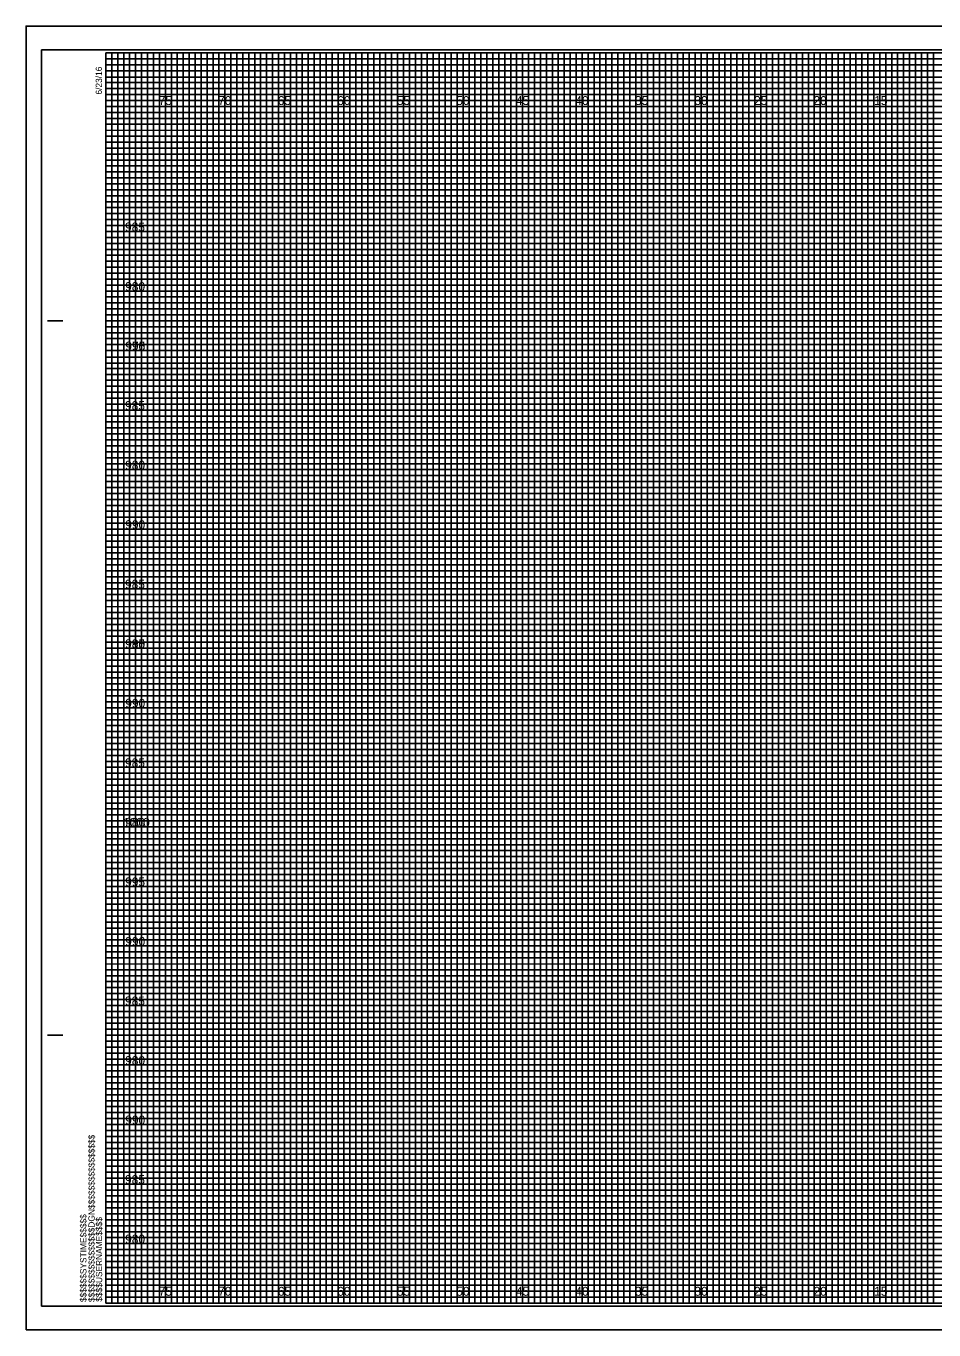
# Model space of a CAD drawing. Extents: x -7 to 162, y -2 to 107.
# Drawn here: x -6.7 to 69.5, y -2.3 to 107.3 of the extents above; entities that cross this region are included whole.
import ezdxf

# ---------------------------------------------------------------- set-up
doc = ezdxf.new("R2010")
doc.units = 0
for name, color, linetype in [('Prop XS Elevation Labels', 7, 'Continuous'), ('Prop XS Offset Labels', 7, 'Continuous'), ('Sheet Cross Section CELL', 7, 'Continuous'), ('Sheet Cross Section Grid Major CELL', 7, 'Continuous'), ('Sheet Cross Section Grid Middle CELL', 7, 'Continuous'), ('Sheet Cross Section Grid Minor 1 CELL', 7, 'Continuous'), ('Sheet Cross Section Grid Minor 2 CELL', 7, 'Continuous'), ('Sheet Cutting Line CELL', 7, 'Continuous'), ('Sheet DOT Grid CELL', 7, 'Continuous'), ('Sheet Plot Border Inside CELL', 7, 'Continuous'), ('Sheet Plot Border Outside CELL', 7, 'Continuous')]:
    doc.layers.add(name, color=color, linetype=linetype)

msp = doc.modelspace()

# ---------------------------------------------------------------- linework, layer by layer
at = {"layer": 'Sheet Cross Section CELL'}
for p, q in [((-4.9, 82.5), (-3.65, 82.5)), ((-4.85, 82.5), (-3.6, 82.5)), ((-4.9, 22.5), (-3.65, 22.5)), ((-4.85, 22.5), (-3.6, 22.5)), ((0, 0), (0, 0)), ((0, 0), (0, 0)), ((0, 0), (0, 0)), ((0, 0), (0, 0)), ((0, 0), (0, 0)), ((0, 0), (0, 0)), ((0, 0), (0, 0))]:
    msp.add_line(p, q, dxfattribs=at)
msp.add_lwpolyline([(160, 105), (0, 105), (0, 0), (160, 0)], close=True, dxfattribs=at)
at = {"layer": 'Sheet Cross Section Grid Major CELL'}
for p, q in [((5, 105), (0, 105)), ((5, 0), (5, 105)), ((15, 105), (10, 105)), ((10, 105), (10, 0)), ((15, 0), (15, 105)), ((25, 105), (20, 105)), ((20, 105), (20, 0)), ((25, 0), (25, 105)), ((35, 105), (30, 105)), ((30, 105), (30, 0)), ((35, 0), (35, 105)), ((45, 105), (40, 105)), ((40, 105), (40, 0)), ((45, 0), (45, 105)), ((55, 105), (50, 105)), ((50, 105), (50, 0)), ((55, 0), (55, 105)), ((65, 105), (60, 105)), ((60, 105), (60, 0)), ((65, 0), (65, 105)), ((10, 0), (5, 0)), ((20, 0), (15, 0)), ((30, 0), (25, 0)), ((40, 0), (35, 0)), ((50, 0), (45, 0)), ((60, 0), (55, 0)), ((70, 0), (65, 0))]:
    msp.add_line(p, q, dxfattribs=at)
for points in [[(0, 100), (160, 100), (160, 95), (0, 95)], [(0, 90), (160, 90), (160, 85), (0, 85)], [(0, 80), (160, 80), (160, 75), (0, 75)], [(0, 70), (160, 70), (160, 65), (0, 65)], [(0, 60), (160, 60), (160, 55), (0, 55)], [(0, 50), (160, 50), (160, 45), (0, 45)], [(0, 40), (160, 40), (160, 35), (0, 35)], [(0, 30), (160, 30), (160, 25), (0, 25)], [(0, 20), (160, 20), (160, 15), (0, 15)], [(0, 10), (160, 10), (160, 5), (0, 5)]]:
    msp.add_lwpolyline(points, dxfattribs=at)
at = {"layer": 'Sheet Cross Section Grid Middle CELL'}
for points in [[(0, 105), (2.5, 105), (2.5, 0), (7.5, 0), (7.5, 105), (12.5, 105), (12.5, 0), (17.5, 0), (17.5, 105), (22.5, 105), (22.5, 0), (27.5, 0), (27.5, 105), (32.5, 105), (32.5, 0), (37.5, 0), (37.5, 105), (42.5, 105), (42.5, 0), (47.5, 0), (47.5, 105), (52.5, 105), (52.5, 0), (57.5, 0), (57.5, 105), (62.5, 105), (62.5, 0), (67.5, 0), (67.5, 105), (72.5, 105)], [(0, 102.5), (137.5, 102.5)], [(0, 92.5), (160, 92.5), (160, 97.5), (0, 97.5)], [(0, 82.5), (160, 82.5), (160, 87.5), (0, 87.5)], [(0, 72.5), (160, 72.5), (160, 77.5), (0, 77.5)], [(0, 62.5), (160, 62.5), (160, 67.5), (0, 67.5)], [(0, 52.5), (160, 52.5), (160, 57.5), (0, 57.5)], [(0, 42.5), (160, 42.5), (160, 47.5), (0, 47.5)], [(0, 32.5), (160, 32.5), (160, 37.5), (0, 37.5)], [(0, 22.5), (160, 22.5), (160, 27.5), (0, 27.5)], [(0, 12.5), (160, 12.5), (160, 17.5), (0, 17.5)], [(0, 2.5), (160, 2.5), (160, 7.5), (0, 7.5)]]:
    msp.add_lwpolyline(points, dxfattribs=at)
at = {"layer": 'Sheet Cross Section Grid Minor 1 CELL'}
for p, q in [((0, 104.5), (130, 104.5)), ((130, 103.99), (0, 103.99)), ((0, 103.99), (0, 103.5)), ((0, 103.5), (130, 103.5)), ((130, 102.95), (0, 102.95)), ((0, 102.95), (0, 102)), ((0, 102), (160, 102))]:
    msp.add_line(p, q, dxfattribs=at)
for points in [[(0, 101.5), (135, 101.5), (160, 101.5), (160, 101), (0, 101)], [(0, 100.5), (160, 100.5), (160, 99.5), (0, 99.5)], [(0, 99), (160, 99), (160, 98.5), (0, 98.49)], [(0, 98), (160, 98), (160, 97), (0, 97)], [(0, 96.5), (160, 96.5), (160, 96), (0, 96)], [(0, 95.5), (160, 95.5), (160, 94.5), (0, 94.5)], [(0, 94), (160, 94), (160, 93.5), (0, 93.5)], [(0, 93), (160, 93), (160, 92), (0, 92)], [(0, 91.5), (160, 91.5), (160, 91), (0, 91)], [(0, 90.5), (160, 90.5), (160, 89.5), (0, 89.5)], [(0, 89), (160, 89), (160, 88.5), (0, 88.5)], [(0, 88), (160, 88), (160, 86.98), (160, 86.5), (160, 86), (0, 86)], [(0, 87), (160, 87), (160, 86.5), (0, 86.5)], [(0, 85.5), (160, 85.5), (160, 84.5), (0, 84.52)], [(0, 84.52), (160, 84.5), (160, 84), (0, 84)], [(0, 83.5), (160, 83.5), (160, 83), (0, 83)], [(0, 82), (160, 82), (160, 81.5), (0, 81.5)], [(0, 81), (160, 81), (160, 80.5), (0, 80.5)], [(-0.04, 79.45), (160, 79.45), (160, 78.94), (-0.04, 78.94)], [(0, 78.5), (160, 78.5), (160, 78), (0, 78)], [(0, 77), (160, 77), (160, 76.5), (0, 76.5)], [(0, 76), (160, 76), (160, 75.5), (0, 75.5)], [(0, 74.5), (160, 74.5), (160, 74), (0, 74)], [(0, 73.5), (160, 73.5), (160, 73), (0, 73)], [(0, 72), (160, 72), (160, 71.5), (0, 71.5)], [(0, 71), (160, 71), (160, 70.5), (0, 70.5)], [(0, 69.5), (160, 69.5), (160, 68.99), (0, 69)], [(0, 68.5), (160, 68.5), (160, 68), (0, 68)], [(0, 67), (160, 67), (160, 66.5), (0, 66.5)], [(0, 66), (160, 66), (160, 65.5), (0, 65.5)], [(0, 64.5), (160, 64.5), (160, 64), (0, 64)], [(0, 63.5), (160, 63.5), (160, 63), (0, 63)], [(0, 62), (160, 62), (160, 61.5), (0, 61.5)], [(0, 61), (160, 61), (160, 60.5), (0, 60.5)], [(0, 59.5), (160, 59.5), (160, 59), (0, 59)], [(0, 58.5), (160.03, 58.45), (160, 58), (0, 58)], [(0, 57), (160, 57), (160, 56.5), (0, 56.5)], [(0, 56), (160, 56), (160, 55.5), (0, 55.5)], [(0, 54.5), (160, 54.5), (160, 54), (0, 54)], [(0, 53.5), (160, 53.5), (160, 53), (0, 53)], [(0, 52), (160, 52), (160, 51.5), (0, 51.5)], [(0, 51), (160, 51), (160, 50.5), (0, 50.5)], [(0, 49.5), (160, 49.5), (160, 49), (0, 49)], [(0, 48.5), (160, 48.5), (160, 48), (0, 48)], [(0, 47), (160, 47), (160, 46.5), (0, 46.5)], [(0, 46), (160, 46), (160, 45.5), (0, 45.5)], [(0, 44.5), (160, 44.5), (160, 44), (0, 44)], [(0, 43.5), (160, 43.5), (160, 43), (0, 43)], [(0, 42), (160, 42), (160, 41.5), (0, 41.5)], [(0, 41), (160, 41), (160, 40.5), (0, 40.5)], [(0, 39.5), (160, 39.5), (160, 38.99), (0, 39)], [(0, 38.5), (160, 38.5), (160, 38), (0, 38)], [(0, 37), (160, 37), (160, 36.5), (0, 36.5)], [(0, 36), (160, 36), (160, 35.5), (0, 35.5)], [(0, 34.5), (160, 34.5), (160, 34), (0, 34)], [(0, 33.5), (160, 33.5), (160, 33), (0, 33)], [(0, 32), (160, 32), (160, 31.5), (0, 31.5)], [(0, 31), (160, 31), (160, 30.5), (0, 30.5)], [(0, 29.5), (160, 29.5), (160, 29), (0, 29)], [(0, 28.5), (160.03, 28.46), (160, 28), (0, 28)], [(0, 27), (160, 27), (160, 26.5), (0, 26.5)], [(0, 26), (160, 26), (160, 25.5), (0, 25.5)], [(0, 24.5), (160, 24.5), (160, 24), (0, 24)], [(0, 23.5), (160, 23.5), (160, 23), (0, 23)], [(0, 22), (160, 22), (160, 21.5), (0, 21.5)], [(0, 21), (160, 21), (160, 20.5), (0, 20.5)], [(0, 19.5), (160, 19.5), (160, 19), (0, 19)], [(0, 18.5), (160, 18.5), (160, 18), (0, 18)], [(0, 17), (160, 17), (160, 16.5), (0, 16.5)], [(0, 16), (160, 16), (160, 15.5), (0, 15.5)], [(0, 14.5), (160, 14.5), (160, 14), (0, 14)], [(0, 13.5), (160, 13.5), (160, 13), (0, 13)], [(0, 12), (160, 12), (160, 11.5), (0, 11.5)], [(0, 11), (160, 11), (160, 10.5), (0, 10.5)], [(0, 9.5), (160, 9.5), (160, 9), (0, 9)], [(0, 8.5), (160, 8.5), (160, 8), (0, 8)], [(0, 7), (160, 7), (160, 6.5), (0, 6.5)], [(0, 6), (160, 6), (160, 5.5), (0, 5.5)], [(0, 4.5), (160, 4.5), (160, 4), (0, 4)], [(0, 3.5), (160, 3.5), (160, 3), (0, 3)], [(0, 2), (160, 2), (160, 1.5), (0, 1.5)], [(0, 1), (160, 1), (160, 0.5), (0, 0.5)]]:
    msp.add_lwpolyline(points, dxfattribs=at)
at = {"layer": 'Sheet Cross Section Grid Minor 2 CELL'}
for points in [[(0, 0), (0.5, 0), (0.5, 105), (1, 105), (1, 0)], [(1, 0), (1.5, 0), (1.5, 105), (2, 105), (2, 0)], [(2.5, 0), (3, 0), (3, 105), (3.5, 105), (3.5, 0)], [(3.5, 0), (4, 0), (4, 105), (4.5, 105), (4.5, 0)], [(5, 0), (5.5, 0), (5.5, 105), (6, 105), (6, 0)], [(6, 0), (6.5, 0), (6.5, 105), (7, 105), (7, 0)], [(7.5, 0), (8, 0), (8, 105), (8.5, 105), (8.5, 0)], [(8.5, 0), (9, 0), (9, 105), (9.5, 105), (9.5, 0)], [(10, 0), (10.5, 0), (10.5, 105), (11, 105), (11, 0)], [(11, 0), (11.5, 0), (11.5, 105), (12, 105), (12, 0)], [(12.5, 0), (13, 0), (13, 105), (13.5, 105), (13.5, 0)], [(13.5, 0), (14, 0), (14, 105), (14.5, 105), (14.5, 0)], [(15, 0), (15.5, 0), (15.5, 105), (16, 105), (16, 0)], [(16, 0), (16.5, 0), (16.5, 105), (17, 105), (17, 0)], [(17.5, 0), (18, 0), (18, 105), (18.5, 105), (18.5, 0)], [(18.5, 0), (19, 0), (19, 105), (19.5, 105), (19.5, 0)], [(20, 0), (20.5, 0), (20.5, 105), (21, 105), (21, 0)], [(21, 0), (21.5, 0), (21.5, 105), (22, 105), (22, 0)], [(22.5, 0), (23, 0), (23, 105), (23.5, 105), (23.5, 0)], [(23.5, 0), (24, 0), (24, 105), (24.5, 105), (24.5, 0)], [(25, 0), (25.5, 0), (25.5, 105), (26, 105), (26, 0)], [(26, 0), (26.5, 0), (26.5, 105), (27, 105), (27, 0)], [(27.5, 0), (28, 0), (28, 105), (28.5, 105), (28.5, 0)], [(28.5, 0), (29, 0), (29, 105), (29.5, 105), (29.5, 0)], [(30, 0), (30.5, 0), (30.5, 105), (31, 105), (31, 0)], [(31, 0), (31.5, 0), (31.5, 105), (32, 105), (32, 0)], [(32.5, 0), (33, 0), (33, 105), (33.5, 105), (33.5, 0)], [(33.5, 0), (34, 0), (34, 105), (34.5, 105), (34.5, 0)], [(35, 0), (35.5, 0), (35.5, 105), (36, 105), (36, 0)], [(36, 0), (36.5, 0), (36.5, 105), (37, 105), (37, 0)], [(37.5, 0), (38, 0), (38, 105), (38.5, 105), (38.5, 0)], [(38.5, 0), (39, 0), (39, 105), (39.5, 105), (39.5, 0)], [(40, 0), (40.5, 0), (40.5, 105), (41, 105), (41, 0)], [(41, 0), (41.5, 0), (41.5, 105), (42, 105), (42, 0)], [(42.5, 0), (43, 0), (43, 105), (43.5, 105), (43.5, 0)], [(43.5, 0), (44, 0), (44, 105), (44.5, 105), (44.5, 0)], [(45, 0), (45.5, 0), (45.5, 105), (46, 105), (46, 0)], [(46, 0), (46.5, 0), (46.5, 105), (47, 105), (47, 0)], [(47.5, 0), (48, 0), (48, 105), (48.5, 105), (48.5, 0)], [(48.5, 0), (49, 0), (49, 105), (49.5, 105), (49.5, 0)], [(50, 0), (50.5, 0), (50.5, 105), (51, 105), (51, 0)], [(51, 0), (51.5, 0), (51.5, 105), (52, 105), (52, 0)], [(52.5, 0), (53, 0), (53, 105), (53.5, 105), (53.5, 0)], [(53.5, 0), (54, 0), (54, 105), (54.5, 105), (54.5, 0)], [(55, 0), (55.5, 0), (55.5, 105), (56, 105), (56, 0)], [(56, 0), (56.5, 0), (56.5, 105), (57, 105), (57, 0)], [(57.5, 0), (58, 0), (58, 105), (58.5, 105), (58.5, 0)], [(58.5, 0), (59, 0), (59, 105), (59.5, 105), (59.5, 0)], [(60, 0), (60.5, 0), (60.5, 105), (61, 105), (61, 0)], [(61, 0), (61.5, 0), (61.5, 105), (62, 105), (62, 0)], [(62.5, 0), (63, 0), (63, 105), (63.5, 105), (63.5, 0)], [(63.5, 0), (64, 0), (64, 105), (64.5, 105), (64.5, 0)], [(65, 0), (65.5, 0), (65.5, 105), (66, 105), (66, 0)], [(66, 0), (66.5, 0), (66.5, 105), (67, 105), (67, 0)], [(67.5, 0), (68, 0), (68, 105), (68.5, 105), (68.5, 0)], [(68.5, 0), (69, 0), (69, 105), (69.5, 105), (69.5, 0)]]:
    msp.add_lwpolyline(points, dxfattribs=at)
at = {"layer": 'Sheet Cutting Line CELL'}
for p, q in [((161.65, 107.25), (-6.7, 107.25)), ((-6.7, 107.25), (-6.7, -2.25)), ((-6.7, -2.25), (161.65, -2.25))]:
    msp.add_line(p, q, dxfattribs=at)
at = {"layer": 'Sheet DOT Grid CELL'}
for p, q in [((5, 0), (5, 105)), ((10, 0), (10, 105)), ((15, 0), (15, 105)), ((20, 0), (20, 105)), ((25, 0), (25, 105)), ((30, 0), (30, 105)), ((35, 0), (35, 105)), ((40, 0), (40, 105)), ((45, 0), (45, 105)), ((50, 0), (50, 105)), ((55, 0), (55, 105)), ((60, 0), (60, 105)), ((65, 0), (65, 105)), ((0, 100), (160, 100)), ((0, 95), (160, 95)), ((0, 90), (160, 90)), ((0, 85), (160, 85)), ((0, 80), (160, 80)), ((0, 75), (160, 75)), ((0, 70), (160, 70)), ((0, 65), (160, 65)), ((0, 60), (160, 60)), ((0, 55), (160, 55)), ((0, 50), (160, 50)), ((0, 45), (160, 45)), ((0, 40), (160, 40)), ((0, 35), (160, 35)), ((0, 30), (160, 30)), ((0, 25), (160, 25)), ((0, 20), (160, 20)), ((0, 15), (160, 15)), ((0, 10), (160, 10)), ((0, 5), (160, 5))]:
    msp.add_line(p, q, dxfattribs=at)
at = {"layer": 'Sheet Plot Border Inside CELL'}
msp.add_lwpolyline([(-5.4, -0.25), (161.2, -0.25), (161.2, 105.25), (-5.4, 105.25)], close=True, dxfattribs=at)
at = {"layer": 'Sheet Plot Border Outside CELL'}
msp.add_lwpolyline([(-6.7, -2.25), (161.65, -2.25), (161.65, 107.25), (-6.7, 107.25)], close=True, dxfattribs=at)

# ---------------------------------------------------------------- texts
at = {"layer": 'Prop XS Elevation Labels'}
for s, p in [('985', (1.61, 90)), ('980', (1.62, 85)), ('990', (1.63, 80)), ('975', (1.64, 80)), ('985', (1.61, 75)), ('980', (1.62, 70)), ('990', (1.63, 65)), ('985', (1.61, 60)), ('995', (1.62, 55)), ('980', (1.62, 55)), ('990', (1.63, 50)), ('985', (1.61, 45)), ('1000', (1.46, 40)), ('980', (1.62, 40)), ('995', (1.62, 35)), ('990', (1.63, 30)), ('985', (1.61, 25)), ('980', (1.62, 20)), ('990', (1.63, 15)), ('985', (1.61, 10)), ('980', (1.62, 5))]:
    msp.add_text(s, height=0.75, dxfattribs=at).set_placement(p)
at = {"layer": 'Prop XS Offset Labels'}
for s, p in [('75', (4.44, 100.62)), ('70', (9.43, 100.62)), ('65', (14.44, 100.62)), ('60', (19.43, 100.62)), ('55', (24.44, 100.62)), ('50', (29.43, 100.62)), ('45', (34.44, 100.62)), ('40', (39.43, 100.62)), ('35', (44.44, 100.62)), ('30', (49.43, 100.62)), ('25', (54.44, 100.62)), ('20', (59.43, 100.62)), ('15', (64.53, 100.62)), ('75', (4.44, 0.62)), ('70', (9.43, 0.62)), ('65', (14.44, 0.62)), ('60', (19.43, 0.62)), ('55', (24.44, 0.62)), ('50', (29.43, 0.62)), ('45', (34.44, 0.62)), ('40', (39.43, 0.62)), ('35', (44.44, 0.62)), ('30', (49.43, 0.62)), ('25', (54.44, 0.62)), ('20', (59.43, 0.62)), ('15', (64.53, 0.62))]:
    msp.add_text(s, height=0.75, dxfattribs=at).set_placement(p)
at = {"layer": 'Sheet Cross Section CELL'}
for s, p in [('6/23/16', (-0.33, 101.5)), ('$$$$$$$$$$$$$$$$DGN$$$$$$$$$$$$$$$$', (-0.94, 0.09)), ('$$$$$$SYSTIME$$$$$', (-1.63, 0.09)), ('$$$$USERNAME$$$$', (-0.31, 0.12))]:
    msp.add_text(s, height=0.525, rotation=90, dxfattribs=at).set_placement(p)

doc.saveas('drawing.dxf')
